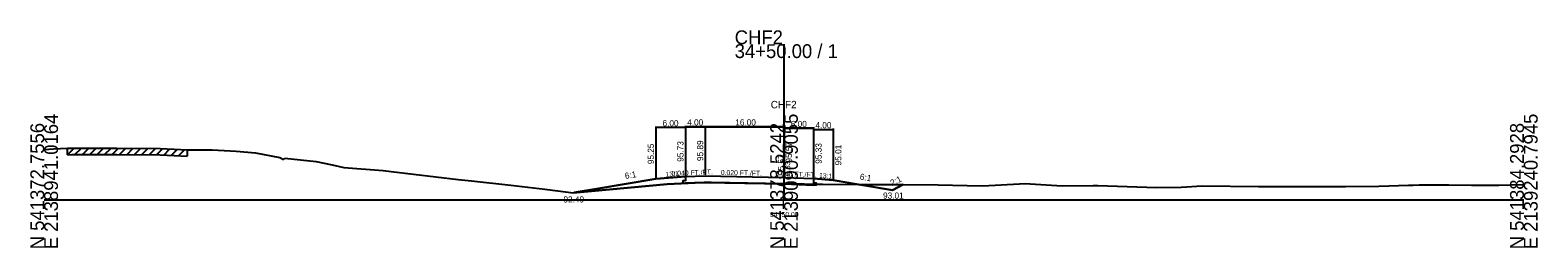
# Model space of a CAD drawing. Extents: x -12831 to 2303, y -10 to 39065.
# Drawn here: x 997.2 to 1302.8, y 8990.3 to 9034.4 of the extents above; entities that cross this region are included whole.
import ezdxf

# ---------------------------------------------------------------- set-up
doc = ezdxf.new("R2010")
doc.units = 0
for name, color, linetype in [('Level 5', 7, 'Continuous'), ('Level 53', 7, 'Continuous'), ('Level 54', 7, 'Continuous'), ('Level 55', 7, 'Continuous'), ('Level 7', 7, 'Continuous'), ('RD_GPK_XS_Cell', 7, 'Continuous'), ('RD_XS_EwShp', 7, 'Continuous'), ('RD_XS_ExGround', 7, 'Continuous'), ('RD_XS_ExPaveRet', 7, 'Continuous'), ('RD_XS_Pave', 7, 'Continuous'), ('RD_XS_TX_Baseline', 7, 'Continuous'), ('RD_XS_TX_Elev_EX', 7, 'Continuous'), ('RD_XS_TX_Elev_PR', 7, 'Continuous'), ('RD_XS_TX_Station', 7, 'Continuous')]:
    doc.layers.add(name, color=color, linetype=linetype)

msp = doc.modelspace()

# ---------------------------------------------------------------- linework, layer by layer
at = {"layer": 'Level 5'}
for p, q in [((1130, 9003.9), (1129.5, 9003.88)), ((1129.5, 9003.88), (1129.5, 9003.38)), ((1129.5, 9003.38), (1130, 9003.4)), ((1130, 9004.73), (1130, 9003.9)), ((1134, 9003.56), (1130, 9003.4)), ((1134, 9003.56), (1130, 9003.4)), ((1130, 9003.4), (1134, 9003.56)), ((1150, 9003.24), (1134, 9003.56)), ((1150, 9003.24), (1134, 9003.56)), ((1134, 9003.56), (1150, 9003.24)), ((1134, 9003.56), (1150, 9003.24)), ((1156, 9003), (1150, 9003.24)), ((1150, 9003.24), (1156, 9003)), ((1150, 9003.24), (1156, 9003)), ((1156, 9004.33), (1156, 9003.5)), ((1156, 9003.5), (1156.5, 9003.48)), ((1156.5, 9002.98), (1156, 9003)), ((1156.5, 9003.48), (1156.5, 9002.98))]:
    msp.add_line(p, q, dxfattribs=at)
at = {"layer": 'Level 54'}
for p, q in [((1124, 9014.88), (1124, 9004.45)), ((1130, 9014.68), (1124, 9014.68)), ((1130, 9015.04), (1130, 9004.93)), ((1130, 9015.04), (1130, 9004.93)), ((1130, 9015.04), (1130, 9004.93)), ((1130, 9014.88), (1130, 9004.93)), ((1130, 9014.84), (1134, 9014.84)), ((1130, 9014.84), (1134, 9014.84)), ((1134, 9014.84), (1130, 9014.84)), ((1134, 9015.04), (1134, 9005.09)), ((1134, 9015.04), (1134, 9005.09)), ((1134, 9015.04), (1134, 9005.09)), ((1134, 9015.04), (1134, 9005.09)), ((1134, 9015.04), (1134, 9005.09)), ((1134, 9015.04), (1134, 9005.09)), ((1134, 9015.04), (1134, 9005.09)), ((1134, 9014.84), (1150, 9014.84)), ((1134, 9014.84), (1150, 9014.84)), ((1150, 9014.84), (1134, 9014.84)), ((1150, 9014.84), (1134, 9014.84)), ((1150, 9015.04), (1150, 9004.77)), ((1150, 9015.04), (1150, 9004.77)), ((1150, 9015.04), (1150, 9004.77)), ((1150, 9015.04), (1150, 9004.77)), ((1150, 9014.72), (1150, 9004.77)), ((1150, 9014.72), (1150, 9004.77)), ((1150, 9014.72), (1150, 9004.77)), ((1156, 9014.72), (1156, 9004.53)), ((1156, 9014.72), (1156, 9004.53)), ((1156, 9014.72), (1156, 9004.53)), ((1150, 9014.52), (1156, 9014.52)), ((1156, 9014.52), (1150, 9014.52)), ((1156, 9014.52), (1150, 9014.52)), ((1156, 9014.48), (1156, 9004.53)), ((1156, 9014.28), (1160, 9014.28)), ((1160, 9014.48), (1160, 9004.21))]:
    msp.add_line(p, q, dxfattribs=at)
at = {"layer": 'Level 7'}
for p, q in [((1124, 9004.25), (1112, 9002.25)), ((1130, 9004.73), (1124, 9004.25)), ((1156, 9004.33), (1160, 9004.01)), ((1160, 9004.01), (1172, 9002.01)), ((1172, 9002.01), (1174.17, 9003.1)), ((1112, 9002.25), (1107.44, 9001.49))]:
    msp.add_line(p, q, dxfattribs=at)
at = {"layer": 'RD_GPK_XS_Cell'}
for p, q in [((1150, 9000), (1150, 9031.55)), ((1000, 9000), (1150, 9000)), ((1150, 9000), (1300, 9000))]:
    msp.add_line(p, q, dxfattribs=at)
at = {"layer": 'RD_XS_EwShp'}
for points in [[(1130, 9003.9), (1129.5, 9003.88), (1129.5, 9003.38), (1130, 9003.4), (1131.83, 9003.47), (1126.34, 9003.18), (1110.98, 9001.78), (1107.44, 9001.49), (1112, 9002.25), (1124, 9004.25), (1130, 9004.73)], [(1133.43, 9003.55), (1133.8, 9003.55), (1131.83, 9003.47)], [(1134, 9003.56), (1133.8, 9003.55), (1135.24, 9003.53)], [(1156, 9003), (1150, 9003.24), (1135.24, 9003.53), (1135.41, 9003.53), (1148.66, 9003.37), (1150, 9003.33), (1150.39, 9003.32), (1156.5, 9003.23), (1156.5, 9002.98)], [(1156.5, 9003.23), (1161.58, 9003.15), (1163.63, 9003.17), (1165.1, 9003.16), (1160, 9004.01), (1156, 9004.33), (1156, 9003.5), (1156.5, 9003.48)], [(1166.17, 9003.15), (1174.17, 9003.1), (1172, 9002.01), (1165.1, 9003.16)]]:
    msp.add_lwpolyline(points, close=True, dxfattribs=at)
at = {"layer": 'RD_XS_ExGround'}
for p, q in [((1000, 9010.25), (1001.88, 9010.35)), ((1001.88, 9010.35), (1004.75, 9010.47)), ((1004.75, 9010.47), (1005.6, 9010.49)), ((1005.6, 9010.49), (1007.53, 9010.52)), ((1007.53, 9010.52), (1014.7, 9010.48)), ((1014.7, 9010.48), (1023.49, 9010.43)), ((1023.49, 9010.43), (1026.37, 9010.31)), ((1026.37, 9010.31), (1028.99, 9010.18)), ((1028.99, 9010.18), (1032.31, 9010.18)), ((1032.31, 9010.18), (1034.05, 9010.15)), ((1034.05, 9010.15), (1038.92, 9009.9)), ((1038.92, 9009.9), (1042.83, 9009.53)), ((1042.83, 9009.53), (1047.8, 9008.63)), ((1047.8, 9008.63), (1048.51, 9008.18)), ((1048.51, 9008.18), (1048.82, 9008.49)), ((1048.82, 9008.49), (1055.17, 9007.81)), ((1055.17, 9007.81), (1058.38, 9007.09)), ((1058.38, 9007.09), (1060.74, 9006.57)), ((1060.74, 9006.57), (1068.71, 9006)), ((1068.71, 9006), (1070.37, 9005.8)), ((1070.37, 9005.8), (1083.93, 9004.14)), ((1083.93, 9004.14), (1086.66, 9003.87)), ((1086.66, 9003.87), (1094.6, 9002.99)), ((1094.6, 9002.99), (1101.54, 9002.17)), ((1110.98, 9001.78), (1126.34, 9003.18)), ((1126.34, 9003.18), (1133.43, 9003.55)), ((1133.43, 9003.55), (1135.41, 9003.53)), ((1135.41, 9003.53), (1148.66, 9003.37)), ((1148.66, 9003.37), (1150, 9003.33)), ((1150, 9003.33), (1150.39, 9003.32)), ((1150.39, 9003.32), (1161.58, 9003.15)), ((1161.58, 9003.15), (1163.63, 9003.17)), ((1163.63, 9003.17), (1166.17, 9003.15)), ((1166.17, 9003.15), (1181.25, 9003.04)), ((1181.25, 9003.04), (1187.15, 9002.93)), ((1187.15, 9002.93), (1190.28, 9002.88)), ((1190.28, 9002.88), (1197.76, 9003.26)), ((1197.76, 9003.26), (1198.98, 9003.33)), ((1198.98, 9003.33), (1199.93, 9003.29)), ((1199.93, 9003.29), (1206.38, 9002.89)), ((1206.38, 9002.89), (1212.71, 9002.93)), ((1212.71, 9002.93), (1213.63, 9002.93)), ((1213.63, 9002.93), (1225.5, 9002.5)), ((1225.5, 9002.5), (1230.49, 9002.62)), ((1230.49, 9002.62), (1234.76, 9002.86)), ((1234.76, 9002.86), (1246.18, 9002.73)), ((1246.18, 9002.73), (1248.93, 9002.74)), ((1248.93, 9002.74), (1251.06, 9002.73)), ((1251.06, 9002.73), (1256.25, 9002.72)), ((1256.25, 9002.72), (1262.65, 9002.72)), ((1262.65, 9002.72), (1263.85, 9002.72)), ((1263.85, 9002.72), (1270.62, 9002.82)), ((1270.62, 9002.82), (1276.63, 9003.01)), ((1276.63, 9003.01), (1277.59, 9003.02)), ((1277.59, 9003.02), (1278.8, 9003.06)), ((1278.8, 9003.06), (1284.78, 9003.07)), ((1284.78, 9003.07), (1289.41, 9003.01)), ((1289.41, 9003.01), (1291.82, 9003.03)), ((1291.82, 9003.03), (1294.91, 9003.03)), ((1294.91, 9003.03), (1300, 9003.14)), ((1101.54, 9002.17), (1104.16, 9001.82)), ((1104.16, 9001.82), (1107.22, 9001.47)), ((1107.22, 9001.47), (1110.98, 9001.78))]:
    msp.add_line(p, q, dxfattribs=at)
at = {"layer": 'RD_XS_ExPaveRet'}
for p, q in [((1004.75, 9009.17), (1006.08, 9010.5)), ((1004.75, 9009.17), (1004.75, 9010.47)), ((1004.75, 9009.17), (1005.6, 9009.19)), ((1005.6, 9009.19), (1007.53, 9009.22)), ((1006.25, 9009.2), (1007.57, 9010.52)), ((1007.53, 9009.22), (1014.7, 9009.18)), ((1007.76, 9009.22), (1009.05, 9010.51)), ((1009.26, 9009.21), (1010.55, 9010.5)), ((1010.76, 9009.2), (1012.05, 9010.49)), ((1012.26, 9009.19), (1013.55, 9010.49)), ((1013.76, 9009.19), (1015.05, 9010.48)), ((1014.7, 9009.18), (1023.49, 9009.13)), ((1015.26, 9009.18), (1016.55, 9010.47)), ((1016.76, 9009.17), (1018.05, 9010.46)), ((1018.26, 9009.16), (1019.55, 9010.45)), ((1019.76, 9009.15), (1021.05, 9010.44)), ((1021.26, 9009.14), (1022.55, 9010.43)), ((1022.76, 9009.13), (1024.03, 9010.41)), ((1023.49, 9009.13), (1026.37, 9009.01)), ((1024.26, 9009.1), (1025.51, 9010.35)), ((1025.76, 9009.04), (1027, 9010.28)), ((1026.37, 9009.01), (1028.99, 9008.88)), ((1027.26, 9008.97), (1028.5, 9010.21)), ((1028.99, 9010.18), (1028.99, 9008.88))]:
    msp.add_line(p, q, dxfattribs=at)
at = {"layer": 'RD_XS_Pave'}
for p, q in [((1130, 9004.73), (1134, 9004.89)), ((1134, 9004.89), (1150, 9004.57)), ((1150, 9004.57), (1156, 9004.33))]:
    msp.add_line(p, q, dxfattribs=at)

# ---------------------------------------------------------------- texts
at = {"layer": 'Level 53'}
for s, rotation, p in [('95.73', 90, (1129.62, 9007.73)), ('95.89', 90, (1133.62, 9007.89)), ('95.89', 90, (1133.62, 9007.89)), ('95.57', 90, (1151.62, 9007.57)), ('95.57', 90, (1151.62, 9007.57)), ('95.25', 90, (1123.62, 9007.25)), ('95.33', 90, (1157.63, 9007.33)), ('95.01', 90, (1161.63, 9007.01)), ('6:1', 9.4623, (1117.84, 9004.24)), ('6:1', 350.5377, (1165.3, 9004.14))]:
    msp.add_text(s, height=1.25, rotation=rotation, dxfattribs=at).set_placement(p)
for s, p in [('92.49', (1105.29, 8999.49)), ('93.01', (1170.08, 9000.26))]:
    msp.add_text(s, height=1.25, dxfattribs=at).set_placement(p)
at = {"layer": 'Level 54'}
for s, p in [('6.00', (1125.37, 9014.93)), ('4.00', (1130.37, 9015.09)), ('4.00', (1130.37, 9015.09)), ('4.00', (1130.37, 9015.09)), ('16.00', (1140.12, 9015.09)), ('16.00', (1140.12, 9015.09)), ('16.00', (1140.12, 9015.09)), ('16.00', (1140.12, 9015.09)), ('6.00', (1151.37, 9014.77)), ('6.00', (1151.37, 9014.77)), ('6.00', (1151.37, 9014.77)), ('4.00', (1156.37, 9014.53))]:
    msp.add_text(s, height=1.25, dxfattribs=at).set_placement(p)
at = {"layer": 'Level 55'}
for s, height, rotation, p in [('13:1', 1, 4.5739, (1126.03, 9004.66)), ('0.040 FT./FT.', 1, 2.2906, (1127.22, 9004.87)), ('0.040 FT./FT.', 1, 2.2906, (1127.22, 9004.87)), ('0.040 FT./FT.', 1, 2.2906, (1127.22, 9004.87)), ('0.020 FT./FT.', 1, 358.8542, (1137.18, 9005.08)), ('0.020 FT./FT.', 1, 358.8542, (1137.18, 9005.08)), ('0.020 FT./FT.', 1, 358.8542, (1137.18, 9005.08)), ('0.020 FT./FT.', 1, 358.8542, (1137.18, 9005.08)), ('0.040 FT./FT.', 1, 357.7094, (1148.24, 9004.89)), ('0.040 FT./FT.', 1, 357.7094, (1148.24, 9004.89)), ('0.040 FT./FT.', 1, 357.7094, (1148.24, 9004.89)), ('13:1', 1, 355.4261, (1157.07, 9004.5)), ('2:1', 1.25, 26.5651, (1171.91, 9002.8))]:
    msp.add_text(s, height=height, rotation=rotation, dxfattribs=at).set_placement(p)
at = {"layer": 'RD_GPK_XS_Cell'}
for s, p in [('CHF2', (1140, 9031.55)), ('34+50.00 / 1', (1140, 9028.75))]:
    msp.add_text(s, height=2.8, dxfattribs=at).set_placement(p)
for s, p in [('N 541372.7556', (1000, 8990)), ('E 2138941.0164', (1002.8, 8990)), ('N 541378.5242', (1150, 8990)), ('E 2139090.9055', (1152.8, 8990)), ('N 541384.2928', (1300, 8990)), ('E 2139240.7945', (1302.8, 8990))]:
    msp.add_text(s, height=2.8, rotation=90, dxfattribs=at).set_placement(p)
at = {"layer": 'RD_XS_TX_Baseline'}
msp.add_text('CHF2', height=1.5, dxfattribs=at).set_placement((1147.31, 9018.57))
at = {"layer": 'RD_XS_TX_Elev_EX'}
msp.add_text('94.33', height=1, rotation=90, dxfattribs=at).set_placement((1151.25, 9004.33))
at = {"layer": 'RD_XS_TX_Elev_PR'}
msp.add_text(' 95.57', height=1.25, rotation=90, dxfattribs=at).set_placement((1150, 9004.57))
at = {"layer": 'RD_XS_TX_Station'}
msp.add_text('34+50.00', height=1, dxfattribs=at).set_placement((1147.15, 8996.57))

doc.saveas('drawing.dxf')
